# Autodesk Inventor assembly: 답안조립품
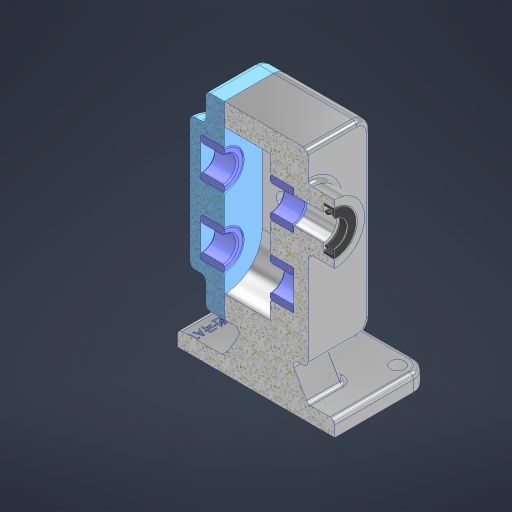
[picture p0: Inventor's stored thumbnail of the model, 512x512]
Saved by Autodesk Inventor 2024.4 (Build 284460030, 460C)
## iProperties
Created: 2026-10
Part Number: 답안조립품
Document SubType Name: Assembly
Designer: user
Author: user
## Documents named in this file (5)
- C:\Users\user\Desktop\761003V1005\답안조립품.iam
- C:\Users\user\Desktop\761003V1005\본체.ipt
- C:\Users\user\Desktop\761003V1005\커버\커버\커버.ipt
- C:\Users\user\Desktop\761003V1005\베어링 부시\베어링 부시\베어링 부시.ipt
- C:\Users\user\Desktop\761003V1005\오일 실 16 28 7\오일 실 16 28 7\오일 실 16 28 7.ipt
